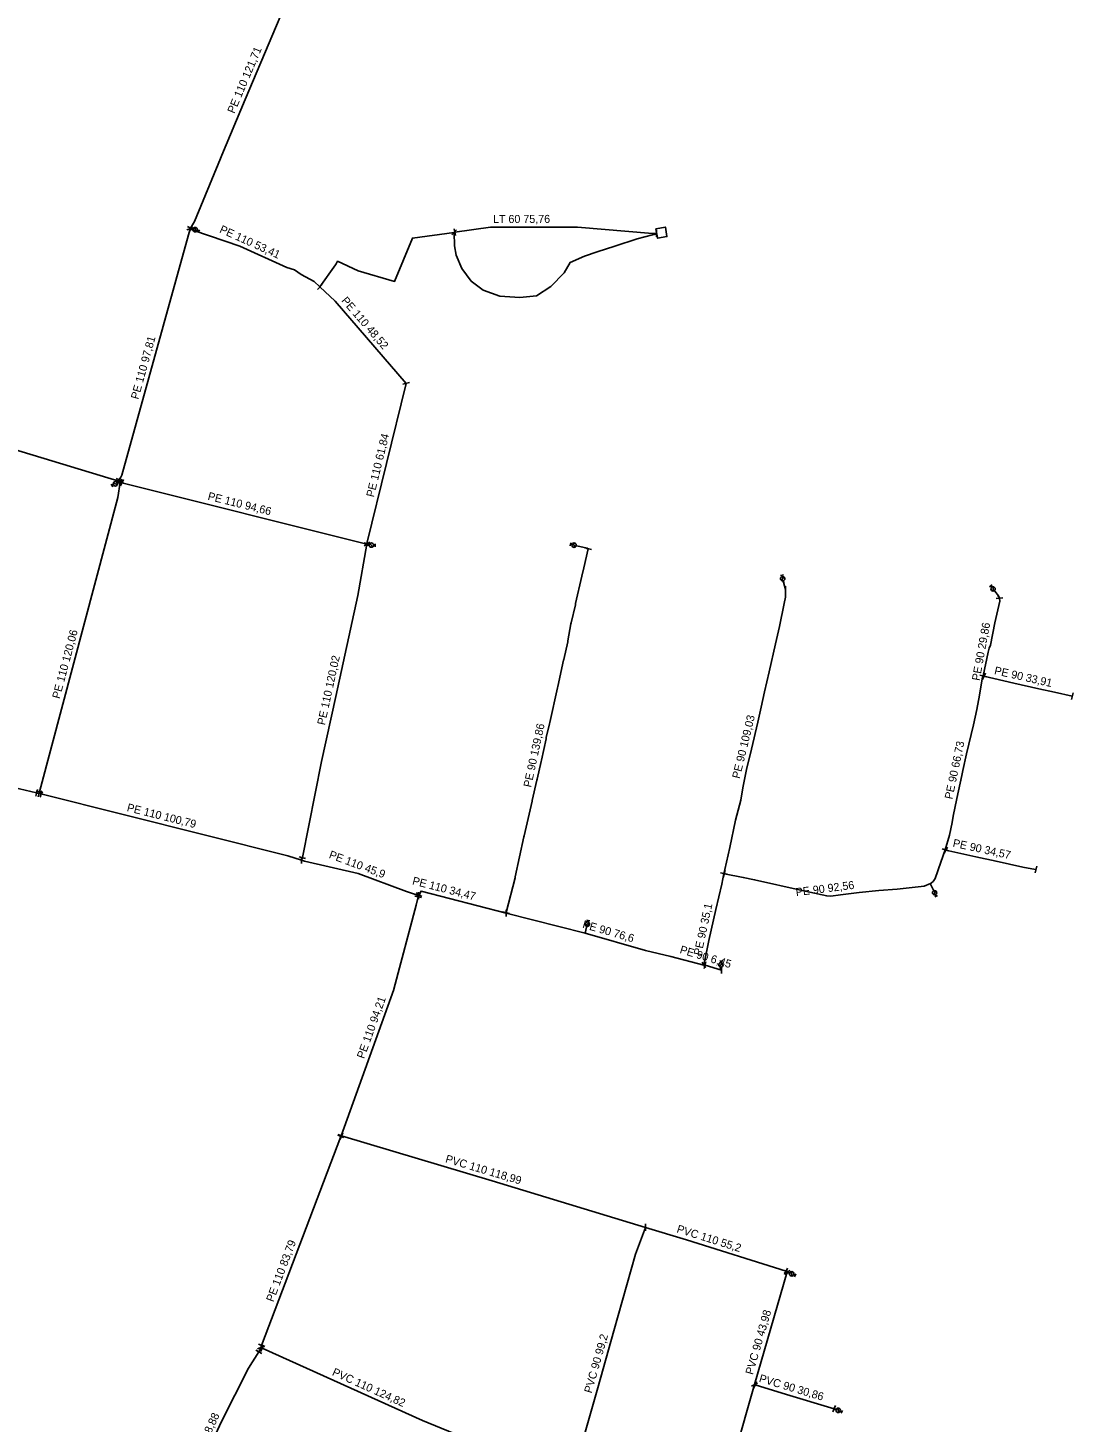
# Model space of a CAD drawing. Extents: x -736619 to -735426, y -1033122 to -1031044.
# Drawn here: x -735818 to -735426, y -1032292 to -1031769 of the extents above; entities that cross this region are included whole.
import ezdxf

# ---------------------------------------------------------------- set-up
doc = ezdxf.new("R2010")
doc.units = 0
for name, color, linetype in [('Vrstva 1', 7, 'Continuous'), ('Vrstva 17', 7, 'Continuous'), ('Vrstva 25', 7, 'Continuous'), ('Vrstva 29', 7, 'Continuous'), ('Vrstva 63', 7, 'Continuous')]:
    doc.layers.add(name, color=color, linetype=linetype)

# ---------------------------------------------------------------- blocks, each defined once
blk = doc.blocks.new('100')
at = {"layer": 'Vrstva 1'}
blk.add_circle((0, 0), 0.127, dxfattribs=at)
blk = doc.blocks.new('133')
at = {"layer": 'Vrstva 1'}
for p, q in [((0.28, 0), (0, 0)), ((0.54, 0.58), (1.7, -0.58)), ((1.94, 0), (2.52, 0)), ((2.52, 0.58), (2.52, -0.58))]:
    blk.add_line(p, q, dxfattribs=at)
blk.add_circle((1.105, 0.003), 0.825, dxfattribs=at)
blk = doc.blocks.new('147')
at = {"layer": 'Vrstva 1'}
blk.add_line((0, 1.27), (0, -1.27), dxfattribs=at)

msp = doc.modelspace()

# ---------------------------------------------------------------- linework, layer by layer
at = {"layer": 'Vrstva 17'}
for p, q in [((-735757.185, -1031844.301), (-735757.048, -1031844.067)), ((-735757.185, -1031844.301), (-735756.954, -1031844.41)), ((-735676.199, -1031902.254), (-735690.898, -1031962.326)), ((-735783.882, -1031938.884), (-735783.775, -1031938.934)), ((-735783.775, -1031938.934), (-735783.652, -1031938.408)), ((-735783.303, -1031939.138), (-735783.775, -1031938.934)), ((-735783.328, -1031939.305), (-735783.303, -1031939.138)), ((-735782.759, -1031939.49), (-735783.303, -1031939.138)), ((-735690.936, -1031962.48), (-735782.759, -1031939.49)), ((-735690.898, -1031962.326), (-735690.936, -1031962.48)), ((-735460.02, -1032011.94), (-735459.71, -1032012.09)), ((-735860.093, -1032044.951), (-735814.679, -1032055.817)), ((-735814.679, -1032055.817), (-735813.807, -1032056.026)), ((-735813.632, -1032055.456), (-735813.807, -1032056.026)), ((-735813.807, -1032056.026), (-735813.105, -1032056.202)), ((-735474.21, -1032077.11), (-735474.03, -1032077.3)), ((-735715.431, -1032081.021), (-735715.116, -1032080.025)), ((-735557.134, -1032086.064), (-735556.959, -1032086.099)), ((-735671.727, -1032094.776), (-735671.618, -1032094.317)), ((-735671.408, -1032093.958), (-735671.618, -1032094.317)), ((-735638.76, -1032100.86), (-735638.71, -1032100.665)), ((-735564.7, -1032120.34), (-735564.24, -1032120.4)), ((-735564.24, -1032120.4), (-735558.06, -1032122.259)), ((-735730.389, -1032262.935), (-735700.702, -1032184.585)), ((-735700.702, -1032184.585), (-735700.615, -1032184.356)), ((-735700.456, -1032184.403), (-735700.615, -1032184.356)), ((-735545.659, -1032277.631), (-735533.453, -1032235.379)), ((-735533.453, -1032235.379), (-735533.848, -1032235.146)), ((-735731.407, -1032265.369), (-735730.717, -1032263.801)), ((-735730.717, -1032263.801), (-735730.389, -1032262.935)), ((-735730.177, -1032264.044), (-735730.717, -1032263.801)), ((-735545.659, -1032277.631), (-735560.511, -1032329.043)), ((-735545.659, -1032277.631), (-735545.411, -1032277.709))]:
    msp.add_line(p, q, dxfattribs=at)
for points in [[(-735757.048, -1031844.067), (-735755.576, -1031841.55), (-735745.782, -1031817.886), (-735745.272, -1031816.655), (-735736.558, -1031795.833), (-735711.687, -1031737.022), (-735709.487, -1031732.061)], [(-735657.964, -1031845.593), (-735644.599, -1031843.733), (-735612.033, -1031843.673), (-735583.901, -1031846.106), (-735582.434, -1031846.091)], [(-735783.652, -1031938.408), (-735782.745, -1031936.721), (-735757.185, -1031844.301)], [(-735756.954, -1031844.41), (-735755.75, -1031844.977), (-735738.608, -1031850.849), (-735720.931, -1031858.835), (-735718.006, -1031859.684), (-735715.511, -1031861.379), (-735710.719, -1031864.098), (-735708.516, -1031866.123)], [(-735708.516, -1031866.123), (-735702.72, -1031857.793), (-735702.512, -1031857.404), (-735701.928, -1031856.494), (-735694.215, -1031860.095), (-735680.562, -1031864.001), (-735673.901, -1031847.81), (-735658.227, -1031845.629)], [(-735658.227, -1031845.629), (-735658.17, -1031850.65), (-735657.43, -1031854.2), (-735655.32, -1031859.15), (-735651.87, -1031863.9), (-735647.31, -1031867.27), (-735641.18, -1031869.6), (-735637.39, -1031869.805), (-735633.6, -1031870.01), (-735627.33, -1031869.43), (-735621.99, -1031865.93), (-735617.06, -1031860.86), (-735614.83, -1031856.94), (-735609.38, -1031854.51), (-735604.66, -1031852.89), (-735598.02, -1031850.82), (-735589.69, -1031848.08), (-735583.9, -1031846.51), (-735582.307, -1031846.279)], [(-735708.516, -1031866.123), (-735702.794, -1031871.382), (-735676.199, -1031902.254)], [(-735884.095, -1031908.771), (-735827.148, -1031925.838), (-735783.882, -1031938.884)], [(-735813.632, -1032055.456), (-735784.303, -1031945.108), (-735783.328, -1031939.305)], [(-735715.116, -1032080.025), (-735707.945, -1032043.978), (-735702.63, -1032019.627), (-735694.381, -1031981.822), (-735690.936, -1031962.48)], [(-735638.71, -1032100.665), (-735635.4, -1032087.68), (-735635.32, -1032087.29), (-735632.16, -1032072.27), (-735632.03, -1032071.94), (-735629.03, -1032058.84), (-735628.96, -1032058.65), (-735627.21, -1032051.07), (-735627.16, -1032050.69), (-735625.65, -1032044.06), (-735625.55, -1032043.55), (-735623.82, -1032035.49), (-735623.73, -1032035.06), (-735622.49, -1032029.86), (-735622.39, -1032029.42), (-735619.53, -1032016.42), (-735619.359, -1032015.945), (-735617.25, -1032005.99), (-735617.14, -1032005.8), (-735615.65, -1031999.1), (-735615.619, -1031998.817), (-735614.456, -1031992.438), (-735614.34, -1031992.03), (-735612.83, -1031985.24), (-735612.77, -1031984.83), (-735610.44, -1031974.48), (-735609.69, -1031971.44), (-735608.04, -1031964.25)], [(-735534.05, -1031979.6), (-735534.02, -1031982.47), (-735534.59, -1031984.84), (-735536.39, -1031993.43), (-735537.79, -1031999.89), (-735540.14, -1032010.43), (-735541.93, -1032017.96), (-735543.18, -1032023.69), (-735544.4, -1032029.24), (-735546.88, -1032039.46), (-735548.67, -1032046.98), (-735550.08, -1032053.9), (-735550.86, -1032058.53), (-735552.79, -1032066.01), (-735554.88, -1032076.21), (-735556.83, -1032084.57), (-735557.134, -1032086.064)], [(-735460.02, -1032011.94), (-735458.16, -1032003.07), (-735457.905, -1032002.079), (-735457.75, -1032001.48), (-735457.22, -1032000.36), (-735455.681, -1031991.982), (-735453.77, -1031983.87), (-735453.88, -1031982.81)], [(-735474.21, -1032077.11), (-735472.6, -1032071.69), (-735471.66, -1032066.84), (-735471.208, -1032064.538), (-735469.888, -1032057.843), (-735467.99, -1032049.27), (-735467.628, -1032047.422), (-735466.312, -1032041.175), (-735463.592, -1032030.281), (-735462.38, -1032024.54), (-735461.406, -1032019.133), (-735460.36, -1032013.08), (-735460.02, -1032011.94)], [(-735459.71, -1032012.09), (-735448.49, -1032014.65), (-735439.173, -1032016.761), (-735433.34, -1032018), (-735426.626, -1032019.533)], [(-735813.105, -1032056.202), (-735720.517, -1032079.413), (-735715.431, -1032081.021)], [(-735556.959, -1032086.099), (-735549.94, -1032087.49), (-735545.67, -1032088.36), (-735527.88, -1032092.33), (-735520.39, -1032094), (-735518.61, -1032094.42), (-735517.11, -1032094.49), (-735513.47, -1032094.03), (-735506.46, -1032093.11), (-735499.11, -1032092.35), (-735492.19, -1032091.88), (-735482.06, -1032090.77), (-735479.79, -1032089.79), (-735479.329, -1032089.499), (-735478.78, -1032089.07), (-735477.99, -1032087.91), (-735475.869, -1032081.8), (-735474.21, -1032077.11)], [(-735474.03, -1032077.3), (-735462.82, -1032079.74), (-735455.18, -1032081.41), (-735445.19, -1032083.59), (-735440.378, -1032084.471), (-735440.22, -1032084.5)], [(-735715.431, -1032081.021), (-735714.374, -1032081.355), (-735694.173, -1032086.029), (-735676.06, -1032092.804), (-735671.618, -1032094.317)], [(-735557.134, -1032086.064), (-735557.94, -1032090.03), (-735560.24, -1032099.55), (-735562.75, -1032111.17), (-735564.7, -1032120.34)], [(-735638.76, -1032100.86), (-735670.62, -1032092.61), (-735671.408, -1032093.958)], [(-735700.615, -1032184.356), (-735680.872, -1032129.507), (-735680.83, -1032129.39), (-735680.83, -1032129.39), (-735672.467, -1032097.885), (-735671.729, -1032094.782), (-735671.727, -1032094.776)], [(-735564.7, -1032120.34), (-735577.08, -1032117.15), (-735586.54, -1032114.91), (-735609.18, -1032108.35), (-735638.76, -1032100.86)], [(-735586.507, -1032218.681), (-735643.972, -1032201.219), (-735700.456, -1032184.403)], [(-735614.348, -1032313.8), (-735604.432, -1032278.8), (-735598.389, -1032257.469), (-735590.25, -1032228.773), (-735586.507, -1032218.681)], [(-735586.507, -1032218.681), (-735571.156, -1032223.407), (-735533.848, -1032235.146)], [(-735771.902, -1032344.392), (-735760.828, -1032325.055), (-735745.541, -1032291.769), (-735735.296, -1032271.519), (-735731.407, -1032265.369)], [(-735615.597, -1032313.515), (-735670.097, -1032291.157), (-735730.177, -1032264.044)], [(-735515.892, -1032286.697), (-735533.645, -1032281.394), (-735545.411, -1032277.709)]]:
    msp.add_lwpolyline(points, dxfattribs=at)
at = {"layer": 'Vrstva 25'}
msp.add_lwpolyline([(-735582.653, -1031844.296), (-735579.106, -1031843.677), (-735578.487, -1031847.224), (-735582.034, -1031847.843), (-735582.653, -1031844.296)], dxfattribs=at)
at = {"layer": 'Vrstva 63'}
for p, q in [((-735691.004, -1031962.86), (-735690.359, -1031962.866)), ((-735609.18, -1032108.35), (-735608.59, -1032106.08))]:
    msp.add_line(p, q, dxfattribs=at)
for points in [[(-735756.985, -1031843.96), (-735756.678, -1031844.117), (-735756.33, -1031844.208)], [(-735783.656, -1031938.985), (-735783.812, -1031939.215), (-735784.176, -1031939.404)], [(-735608.04, -1031964.25), (-735608.46, -1031964.08), (-735612.23, -1031963.18)], [(-735534.05, -1031979.6), (-735534.84, -1031976.75), (-735534.88, -1031976.57)], [(-735453.88, -1031982.81), (-735454.32, -1031981.97), (-735455.64, -1031980.21)], [(-735479.79, -1032089.79), (-735479.69, -1032089.99), (-735478.67, -1032092.21)], [(-735558.59, -1032122.1), (-735558.43, -1032121.7), (-735558.396, -1032121.354)], [(-735533.453, -1032235.379), (-735533.084, -1032235.589), (-735532.794, -1032235.681)], [(-735515.892, -1032286.697), (-735515.65, -1032286.769), (-735515.398, -1032286.845)]]:
    msp.add_lwpolyline(points, dxfattribs=at)

# ---------------------------------------------------------------- block references
at = {"layer": 'Vrstva 25'}
for p, xscale, yscale, rotation in [((-735756.33, -1031844.208), 1.0365458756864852, 1.0365458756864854, -21.97149085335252), ((-735784.176, -1031939.404), 1.0138864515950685, 1.0138864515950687, -152.4346848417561), ((-735690.359, -1031962.866), 0.9999999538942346, 0.9999999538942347, -2.0000000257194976), ((-735612.23, -1031963.18), 1.0028916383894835, 1.0028916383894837, 166.30279209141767), ((-735534.88, -1031976.57), 0.9999999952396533, 0.9999999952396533, 102.9999994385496), ((-735455.64, -1031980.21), 0.9999999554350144, 0.9999999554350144, 126.99999920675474), ((-735478.67, -1032092.21), 0.9999999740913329, 0.9999999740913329, -65.99999939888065), ((-735608.59, -1032106.08), 0.999999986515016, 0.9999999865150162, 74.99999987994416), ((-735558.396, -1032121.354), 1.0011216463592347, 1.0011216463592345, 83.41738977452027), ((-735532.794, -1032235.681), 1.0316957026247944, 1.0316957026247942, -23.584588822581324), ((-735515.398, -1032286.845), 1.0335064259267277, 1.033506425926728, -23.04128150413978)]:
    msp.add_blockref('133', p, dxfattribs=dict(at, xscale=xscale, yscale=yscale, rotation=rotation))
at = {"layer": 'Vrstva 29'}
for p, xscale, yscale, rotation in [((-735757.048, -1031844.067), 0.9999999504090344, 0.9999999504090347, -121.00000158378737), ((-735756.954, -1031844.41), 1.0169561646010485, 1.0169561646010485, 153.0239835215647), ((-735757.185, -1031844.301), 0.9999999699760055, 0.9999999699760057, 106.99999966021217), ((-735658.227, -1031845.629), 0.9999999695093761, 0.9999999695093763, 138.9999986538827), ((-735657.964, -1031845.593), 1.0092050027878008, 1.0092050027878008, 11.116918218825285), ((-735582.307, -1031846.279), 1.0098116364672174, 1.0098116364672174, -169.38969904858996), ((-735708.516, -1031866.123), 0.9999999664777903, 0.9999999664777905, 137.00000193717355), ((-735676.199, -1031902.254), 0.9999999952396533, 0.9999999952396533, -77.00000056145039), ((-735783.652, -1031938.408), 0.9999999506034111, 0.9999999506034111, -112.00000028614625), ((-735783.882, -1031938.884), 1.0275072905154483, 1.027507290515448, 155.31089431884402), ((-735783.775, -1031938.934), 0.999999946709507, 0.999999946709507, 117.00000088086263), ((-735783.328, -1031939.305), 0.9999999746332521, 0.9999999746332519, -99.99999944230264), ((-735783.303, -1031939.138), 0.9999999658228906, 0.9999999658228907, -62.00000017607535), ((-735782.759, -1031939.49), 1.022584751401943, 1.022584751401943, 154.18102569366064), ((-735690.898, -1031962.326), 0.999999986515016, 0.9999999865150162, -105.00000012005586), ((-735690.936, -1031962.48), 0.9999999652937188, 0.9999999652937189, -58.00000261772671), ((-735608.04, -1031964.25), 0.9999999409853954, 0.9999999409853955, -104.00000032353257), ((-735453.88, -1031982.81), 1.0011216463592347, 1.0011216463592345, 96.58261022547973), ((-735459.71, -1032012.09), 1.0296949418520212, 1.0296949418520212, -24.133789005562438), ((-735460.02, -1032011.94), 0.9999999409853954, 0.9999999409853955, 75.99999967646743), ((-735426.626, -1032019.533), 1.0009847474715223, 1.0009847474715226, -14.22432628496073), ((-735814.679, -1032055.817), 1.0028916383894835, 1.0028916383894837, 166.30279209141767), ((-735813.632, -1032055.456), 0.9999999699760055, 0.9999999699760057, -106.99999966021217), ((-735813.807, -1032056.026), 1.0009847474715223, 1.0009847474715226, 165.7756737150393), ((-735813.105, -1032056.202), 1.0009847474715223, 1.0009847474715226, 165.7756737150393), ((-735474.21, -1032077.11), 0.9999999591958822, 0.9999999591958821, 72.00000054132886), ((-735474.03, -1032077.3), 0.9999999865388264, 0.9999999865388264, -30.00000044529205), ((-735715.116, -1032080.025), 0.9999999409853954, 0.9999999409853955, 75.99999967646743), ((-735440.22, -1032084.5), 1.0060666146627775, 1.0060666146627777, -12.654735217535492), ((-735557.134, -1032086.064), 0.999999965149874, 0.9999999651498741, -102.0000000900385), ((-735556.959, -1032086.099), 1.0045862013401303, 1.00458620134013, -13.17409066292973), ((-735671.727, -1032094.776), 0.9999999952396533, 0.9999999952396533, 77.00000056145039), ((-735671.408, -1032093.958), 0.9999999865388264, 0.9999999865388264, 59.99999955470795), ((-735638.71, -1032100.665), 0.9999999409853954, 0.9999999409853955, 75.99999967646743), ((-735564.7, -1032120.34), 0.9999999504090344, 0.9999999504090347, -148.99999841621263), ((-735564.24, -1032120.4), 1.0045862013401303, 1.00458620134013, 166.82590933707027), ((-735700.456, -1032184.403), 1.0335064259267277, 1.033506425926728, -23.04128150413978), ((-735700.702, -1032184.585), 0.999999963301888, 0.9999999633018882, 69.00000101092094), ((-735700.615, -1032184.356), 0.9999999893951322, 0.9999999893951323, 70.00000094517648), ((-735533.453, -1032235.379), 0.9999999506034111, 0.9999999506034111, 112.00000028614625), ((-735533.848, -1032235.146), 1.0198568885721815, 1.0198568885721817, 153.60601759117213), ((-735731.407, -1032265.369), 0.999999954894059, 0.9999999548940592, -119.00000058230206), ((-735730.717, -1032263.801), 0.9999999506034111, 0.9999999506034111, 112.00000028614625), ((-735730.389, -1032262.935), 0.9999999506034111, 0.9999999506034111, -112.00000028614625), ((-735730.177, -1032264.044), 1.0198568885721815, 1.0198568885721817, 153.60601759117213), ((-735545.659, -1032277.631), 0.999999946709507, 0.999999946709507, -62.999999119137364), ((-735545.411, -1032277.709), 1.0335064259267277, 1.033506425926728, -23.04128150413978), ((-735515.892, -1032286.697), 1.0335064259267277, 1.033506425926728, -23.04128150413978)]:
    msp.add_blockref('147', p, dxfattribs=dict(at, xscale=xscale, yscale=yscale, rotation=rotation))
at = {"layer": 'Vrstva 29', "rotation": 180}
msp.add_blockref('147', (-735582.434, -1031846.091), dxfattribs=at)
at = {"layer": 'Vrstva 29'}
for p in [(-735534.05, -1031979.6), (-735715.431, -1032081.021), (-735671.618, -1032094.317), (-735638.76, -1032100.86), (-735558.06, -1032122.259), (-735586.507, -1032218.681)]:
    msp.add_blockref('147', p, dxfattribs=at)
at = {"layer": 'Vrstva 63'}
for p, xscale, yscale, rotation in [((-735756.678, -1031844.117), 1.025136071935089, 1.0251360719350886, -25.250758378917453), ((-735783.812, -1031939.215), 0.9999999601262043, 0.9999999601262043, 41.999998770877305), ((-735690.675, -1031962.863), 0.9999999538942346, 0.9999999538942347, -2.0000000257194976), ((-735608.46, -1031964.08), 1.0316957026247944, 1.0316957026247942, -23.584588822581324), ((-735534.84, -1031976.75), 0.999999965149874, 0.9999999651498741, -77.9999999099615), ((-735454.32, -1031981.97), 0.9999999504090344, 0.9999999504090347, -58.99999841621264), ((-735479.686, -1032089.998), 0.9999999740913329, 0.9999999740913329, -65.99999939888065), ((-735609.143, -1032108.206), 0.999999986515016, 0.9999999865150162, 74.99999987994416), ((-735558.43, -1032121.7), 0.9999999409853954, 0.9999999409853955, 75.99999967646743), ((-735533.084, -1032235.589), 1.0169561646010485, 1.0169561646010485, -26.97601647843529), ((-735515.65, -1032286.769), 1.0335064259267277, 1.033506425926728, -23.04128150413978)]:
    msp.add_blockref('100', p, dxfattribs=dict(at, xscale=xscale, yscale=yscale, rotation=rotation))

# ---------------------------------------------------------------- texts
for s, height, rotation, p in [('PE 110 121,71', 2.99999, 67.08, (-735740.607, -1031801.303)), ('PE 110 53,41', 2.99999, 335.69, (-735746.417, -1031845.566)), ('LT 60 75,76', 2.99999, 0.11, (-735643.686, -1031842.132)), ('PE 110 48,52', 2.99999, 310.74, (-735700.696, -1031871.364)), ('PE 110 97,81', 2.99999, 74.54, (-735776.585, -1031908.445)), ('PE 110 61,84', 2.99999, 76.25, (-735688.336, -1031945.122)), ('PE 110 94,66', 2.99999, 345.94, (-735750.77, -1031945.848)), ('PE 110 120,06', 2.99999, 75.12, (-735806.05, -1032020.707)), ('PE 90 29,86', 2.99999, 79.59, (-735461.337, -1032013.916)), ('PE 110 120,02', 2.99999, 77.69, (-735706.686, -1032030.563)), ('PE 90 33,91', 2.99999, 347.23, (-735456.055, -1032011.256)), ('PE 90 109,03', 2.99999, 76.36, (-735551.243, -1032050.654)), ('PE 90 139,86', 2.99999, 77.89, (-735629.406, -1032053.899)), ('PE 90 66,73', 2.99999, 78.1, (-735471.569, -1032058.362)), ('PE 110 100,79', 2.99999, 345.93, (-735781.086, -1032062.58)), ('PE 90 34,57', 2.99999, 347.67, (-735471.591, -1032075.934)), ('PE 110 45,9', 2.99999, 339.49, (-735705.399, -1032080.121)), ('PE 110 34,47', 2.99999, 345.48, (-735674.128, -1032090.047)), ('PE 90 92,56', 2.99999, 7.2, (-735530.064, -1032094.511)), ('PE 90 35,1', 3, 77.81, (-735565.632, -1032116.931)), ('PE 90 76,6', 3, 343.84, (-735610.381, -1032106.336)), ('PE 90 6,45', 3, 343.26, (-735573.914, -1032115.819)), ('PE 110 94,21', 2.99999, 70.2, (-735691.995, -1032155.679)), ('PVC 110 118,99', 2.99999, 343.42, (-735661.758, -1032194.253)), ('PVC 110 55,2', 2.99999, 342.53, (-735575.065, -1032220.498)), ('PE 110 83,79', 2.99999, 69.25, (-735726.012, -1032246.871)), ('PVC 90 43,98', 2.99999, 73.89, (-735546.314, -1032274.138)), ('PVC 90 99,2', 2.99999, 74.18, (-735606.738, -1032281.067)), ('PVC 110 124,82', 2.99999, 335.71, (-735704.206, -1032274.004)), ('PVC 90 30,86', 2.99999, 343.37, (-735544.222, -1032276.562)), ('PE 110 88,88', 2.99999, 65.33, (-735756.215, -1032311.177))]:
    msp.add_text(s, height=height, rotation=rotation, dxfattribs=at).set_placement(p)

doc.saveas('drawing.dxf')
